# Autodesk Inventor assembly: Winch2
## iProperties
Author: Administrator
Shininess: 20.0
PropertySet Name: _Private Model Information
Created: 2001-04
Part Number: Winch2
Document SubType Name: Assembly
Designer: Administrator
Control State: 0
Master: False
Checked Out: False
PropertySet Name: Design Tracking Control
Density: 0.0
Volumn: 0.0
Area: 0.0
PropertySet Name: Model Information
